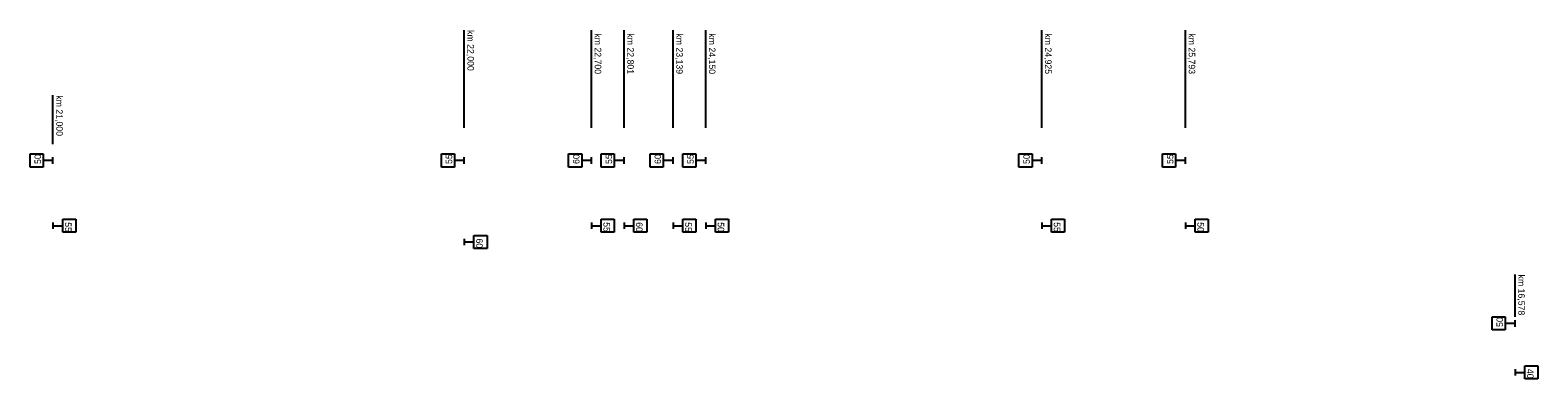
# Model space of a CAD drawing. Extents: x -1424 to 5155, y -2900 to 2050.
# Drawn here: x 4693 to 5155, y 1943 to 2050 of the extents above; entities that cross this region are included whole.
import ezdxf

# ---------------------------------------------------------------- set-up
doc = ezdxf.new("R2010")
doc.units = 0
doc.layers.add('rychlostník', color=7, linetype='Continuous')

msp = doc.modelspace()

# ---------------------------------------------------------------- linework, layer by layer
at = {"layer": 'rychlostník'}
for p, q in [((4826, 2020), (4826, 2050)), ((4865, 2020), (4865, 2050)), ((4865, 2020), (4865, 2050)), ((4875, 2020), (4875, 2050)), ((4875, 2020), (4875, 2050)), ((4890, 2020), (4890, 2050)), ((4890, 2020), (4890, 2050)), ((4900, 2020), (4900, 2050)), ((4900, 2020), (4900, 2050)), ((5003, 2020), (5003, 2050)), ((5003, 2020), (5003, 2050)), ((5047, 2020), (5047, 2050)), ((5047, 2020), (5047, 2050)), ((4700, 2015), (4700, 2030)), ((4693, 2008), (4693, 2012)), ((4693, 2012), (4697, 2012)), ((4697, 2012), (4697, 2008)), ((4700, 2010), (4697, 2010)), ((4700, 2009), (4700, 2011)), ((4819, 2008), (4819, 2012)), ((4819, 2012), (4823, 2012)), ((4821.33, 2010.09), (4821.33, 2010.09)), ((4823, 2012), (4823, 2008)), ((4826, 2010), (4823, 2010)), ((4826, 2009), (4826, 2011)), ((4858, 2008), (4858, 2012)), ((4858, 2012), (4862, 2012)), ((4860.33, 2010.09), (4860.33, 2010.09)), ((4862, 2012), (4862, 2008)), ((4865, 2010), (4862, 2010)), ((4865, 2009), (4865, 2011)), ((4868, 2008), (4868, 2012)), ((4868, 2012), (4872, 2012)), ((4870.33, 2010.09), (4870.33, 2010.09)), ((4872, 2012), (4872, 2008)), ((4875, 2010), (4872, 2010)), ((4875, 2009), (4875, 2011)), ((4883, 2008), (4883, 2012)), ((4883, 2012), (4887, 2012)), ((4885.33, 2010.09), (4885.33, 2010.09)), ((4887, 2012), (4887, 2008)), ((4890, 2010), (4887, 2010)), ((4890, 2009), (4890, 2011)), ((4893, 2008), (4893, 2012)), ((4893, 2012), (4897, 2012)), ((4895.33, 2010.09), (4895.33, 2010.09)), ((4897, 2012), (4897, 2008)), ((4900, 2010), (4897, 2010)), ((4900, 2009), (4900, 2011)), ((4996, 2008), (4996, 2012)), ((4996, 2012), (5000, 2012)), ((4998.33, 2010.09), (4998.33, 2010.09)), ((5000, 2012), (5000, 2008)), ((5003, 2010), (5000, 2010)), ((5003, 2009), (5003, 2011)), ((5040, 2008), (5040, 2012)), ((5040, 2012), (5044, 2012)), ((5042.33, 2010.09), (5042.33, 2010.09)), ((5044, 2012), (5044, 2008)), ((5047, 2010), (5044, 2010)), ((5047, 2009), (5047, 2011)), ((4697, 2008), (4693, 2008)), ((4823, 2008), (4819, 2008)), ((4862, 2008), (4858, 2008)), ((4872, 2008), (4868, 2008)), ((4887, 2008), (4883, 2008)), ((4897, 2008), (4893, 2008)), ((5000, 2008), (4996, 2008)), ((5044, 2008), (5040, 2008)), ((4703, 1992), (4707, 1992)), ((4703, 1988), (4703, 1992)), ((4707, 1992), (4707, 1988)), ((4868, 1992), (4872, 1992)), ((4868, 1988), (4868, 1992)), ((4872, 1992), (4872, 1988)), ((4878, 1992), (4882, 1992)), ((4878, 1988), (4878, 1992)), ((4882, 1992), (4882, 1988)), ((4893, 1992), (4897, 1992)), ((4893, 1988), (4893, 1992)), ((4897, 1992), (4897, 1988)), ((4903, 1992), (4907, 1992)), ((4903, 1988), (4903, 1992)), ((4907, 1992), (4907, 1988)), ((5006, 1992), (5010, 1992)), ((5006, 1988), (5006, 1992)), ((5010, 1992), (5010, 1988)), ((5050, 1992), (5054, 1992)), ((5050, 1988), (5050, 1992)), ((5054, 1992), (5054, 1988)), ((4700, 1991), (4700, 1989)), ((4700, 1990), (4703, 1990)), ((4707, 1988), (4703, 1988)), ((4829, 1987), (4833, 1987)), ((4829, 1983), (4829, 1987)), ((4833, 1987), (4833, 1983)), ((4865, 1991), (4865, 1989)), ((4865, 1990), (4868, 1990)), ((4872, 1988), (4868, 1988)), ((4869.67, 1989.91), (4869.67, 1989.91)), ((4875, 1991), (4875, 1989)), ((4875, 1990), (4878, 1990)), ((4882, 1988), (4878, 1988)), ((4879.67, 1989.91), (4879.67, 1989.91)), ((4890, 1991), (4890, 1989)), ((4890, 1990), (4893, 1990)), ((4897, 1988), (4893, 1988)), ((4894.67, 1989.91), (4894.67, 1989.91)), ((4900, 1991), (4900, 1989)), ((4900, 1990), (4903, 1990)), ((4907, 1988), (4903, 1988)), ((4904.67, 1989.91), (4904.67, 1989.91)), ((5003, 1991), (5003, 1989)), ((5003, 1990), (5006, 1990)), ((5010, 1988), (5006, 1988)), ((5007.67, 1989.91), (5007.67, 1989.91)), ((5047, 1991), (5047, 1989)), ((5047, 1990), (5050, 1990)), ((5054, 1988), (5050, 1988)), ((5051.67, 1989.91), (5051.67, 1989.91)), ((4826, 1986), (4826, 1984)), ((4826, 1985), (4829, 1985)), ((4833, 1983), (4829, 1983)), ((4830.67, 1984.91), (4830.67, 1984.91)), ((5148, 1962), (5148, 1975)), ((5141, 1958), (5141, 1962)), ((5141, 1962), (5145, 1962)), ((5143.33, 1960.09), (5143.33, 1960.09)), ((5145, 1962), (5145, 1958)), ((5148, 1960), (5145, 1960)), ((5148, 1959), (5148, 1961)), ((5145, 1958), (5141, 1958)), ((5148, 1946), (5148, 1944)), ((5151, 1947), (5155, 1947)), ((5151, 1943), (5151, 1947)), ((5155, 1947), (5155, 1943)), ((5148, 1945), (5151, 1945)), ((5155, 1943), (5151, 1943))]:
    msp.add_line(p, q, dxfattribs=at)

# ---------------------------------------------------------------- texts
for s, rotation, p in [('km 22,000', 270, (4827, 2050)), ('km 22,700', 270, (4866, 2049)), ('km 22,801', 270, (4876, 2049)), ('km 23,139', 270, (4891, 2049)), ('km 24,150', 270, (4901, 2049)), ('km 24,925', 270, (5004, 2049)), ('km 25,793', 270, (5048, 2049)), ('km 21,000', 270, (4701, 2030)), ('50', 90, (4696.33, 2008.93)), ('55', 90, (4822.33, 2008.93)), ('60', 90, (4861.33, 2008.93)), ('55', 90, (4871.33, 2008.93)), ('60', 90, (4886.33, 2008.93)), ('55', 90, (4896.33, 2008.93)), ('50', 90, (4999.33, 2008.93)), ('55', 90, (5043.33, 2008.93)), ('55', 270, (4703.67, 1991.07)), ('55', 270, (4868.67, 1991.07)), ('60', 270, (4878.67, 1991.07)), ('55', 270, (4893.67, 1991.07)), ('50', 270, (4903.67, 1991.07)), ('55', 270, (5006.67, 1991.07)), ('50', 270, (5050.67, 1991.07)), ('60', 270, (4829.67, 1986.07)), ('km 16,578', 270, (5149, 1975)), ('50', 90, (5144.33, 1958.93)), ('40', 270, (5151.67, 1946.07))]:
    msp.add_text(s, height=2, rotation=rotation, dxfattribs=at).set_placement(p)

doc.saveas('drawing.dxf')
